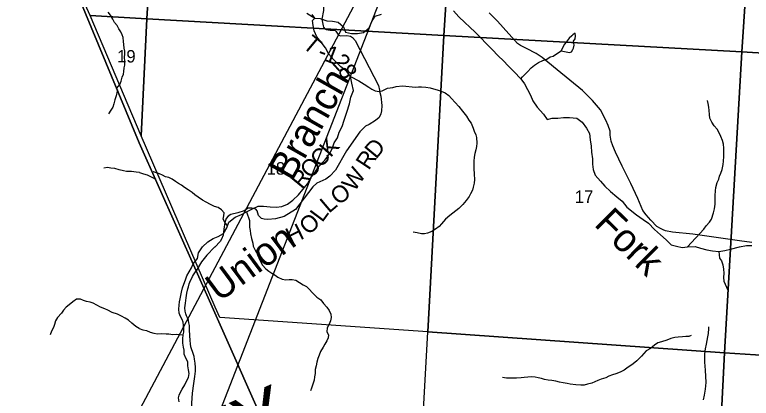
# Model space of a CAD drawing. Extents: x 0 to 34, y 0 to 22.
# Drawn here: x 3.875 to 6.352, y 15.256 to 16.547 of the extents above; entities that cross this region are included whole.
import ezdxf

# ---------------------------------------------------------------- set-up
doc = ezdxf.new("R2010")
doc.units = 0
for name, color, linetype in [('GM_X_County_Text', 7, 'Continuous'), ('GM_X_Minor_Lake', 7, 'Continuous'), ('GM_X_Minor_River', 7, 'Continuous'), ('GM_X_Minor_River_Text', 7, 'Continuous'), ('GM_X_Section', 7, 'Continuous'), ('GM_X_Section_Text', 7, 'Continuous'), ('GM_X_State_Route', 7, 'Continuous'), ('GM_X_Township_Road', 7, 'Continuous'), ('GM_X_Township_Road_Text', 7, 'Continuous'), ('GM_X_Unincorporated', 7, 'Continuous'), ('SH_Cut_Line', 7, 'Continuous'), ('SH_Text', 7, 'Continuous')]:
    doc.layers.add(name, color=color, linetype=linetype)

msp = doc.modelspace()

# ---------------------------------------------------------------- linework, layer by layer
at = {"layer": 'GM_X_Minor_Lake'}
for points in [[(5.7603, 16.4656), (5.761, 16.4766), (5.7595, 16.4853), (5.7523, 16.4789), (5.7482, 16.4755), (5.7402, 16.4683), (5.7296, 16.4547), (5.7231, 16.4471), (5.7126, 16.4254)], [(5.7126, 16.4254), (5.7408, 16.4201), (5.7477, 16.422), (5.7526, 16.4303), (5.7545, 16.4345), (5.7564, 16.4451), (5.7549, 16.4576), (5.7603, 16.4656)]]:
    msp.add_lwpolyline(points, dxfattribs=at)
at = {"layer": 'GM_X_Minor_River'}
for points in [[(4.218, 16.3003), (4.2279, 16.3118), (4.2329, 16.3239), (4.2356, 16.3364), (4.2405, 16.347), (4.2417, 16.3565), (4.2425, 16.3678), (4.2452, 16.3773), (4.2445, 16.3906), (4.2442, 16.4039), (4.245, 16.4141), (4.2447, 16.4247), (4.2425, 16.435), (4.2418, 16.4467), (4.2403, 16.457), (4.2393, 16.4699), (4.2363, 16.4794), (4.2318, 16.4893), (4.225, 16.4995), (4.2187, 16.5106), (4.2104, 16.5212), (4.2044, 16.5319), (4.1969, 16.5456), (4.1886, 16.5555)], [(4.857, 16.5526), (4.8838, 16.535), (4.902, 16.5339), (4.925, 16.527), (4.9436, 16.5259), (4.9625, 16.5224), (4.9806, 16.5068), (4.987, 16.4885), (5.0078, 16.4836), (5.0275, 16.4836), (5.048, 16.4874), (5.0669, 16.5033), (5.0764, 16.5246), (5.0867, 16.5428), (5.1083, 16.5493)], [(5.3506, 16.5601), (5.3691, 16.5399), (5.3887, 16.5212), (5.4061, 16.5056), (5.4235, 16.4881), (5.4431, 16.4691), (5.4609, 16.4508), (5.4805, 16.4299), (5.5009, 16.4086), (5.5187, 16.3922), (5.5345, 16.3751), (5.5553, 16.3549), (5.5772, 16.3317), (5.5893, 16.3142), (5.61, 16.2765), (5.6172, 16.2567), (5.6326, 16.2358), (5.653, 16.2118), (5.6655, 16.1943), (5.6829, 16.1989), (5.7018, 16.1989), (5.7211, 16.2008), (5.7404, 16.2011), (5.7654, 16.1984), (5.7835, 16.1851), (5.7986, 16.1646), (5.8081, 16.1467), (5.8107, 16.1261), (5.8133, 16.1045), (5.8151, 16.0839), (5.8181, 16.0622), (5.818, 16.0444), (5.821, 16.0254), (5.8267, 16.0067), (5.8455, 15.9869), (5.8599, 15.9694), (5.8784, 15.9519), (5.9007, 15.9344), (5.9181, 15.9188), (5.9339, 15.8986), (5.9664, 15.8731), (5.9883, 15.8571), (6.0072, 15.8453), (6.0269, 15.8244), (6.0469, 15.8065)], [(4.4751, 15.7083), (4.489, 15.7259), (4.4924, 15.7449), (4.5061, 15.765), (4.5239, 15.7821), (4.5418, 15.7931), (4.5588, 15.8003), (4.577, 15.811), (4.588, 15.83), (4.5953, 15.8482), (4.6161, 15.8653), (4.6373, 15.874), (4.6548, 15.8835), (4.6741, 15.8938), (4.6931, 15.9021), (4.7112, 15.9021), (4.7336, 15.9002), (4.7544, 15.8994), (4.7729, 15.9017), (4.7923, 15.9093), (4.8101, 15.9222), (4.8298, 15.9404), (4.8442, 15.9583), (4.8594, 15.9776), (4.8704, 15.9974), (4.8845, 16.016), (4.8982, 16.0361), (4.9175, 16.0578), (4.9346, 16.0798), (4.9433, 16.0985), (4.9491, 16.1159), (4.9605, 16.133), (4.9662, 16.1521), (4.9764, 16.1707), (4.9833, 16.1923), (4.9917, 16.219), (5.0005, 16.2471), (5.0058, 16.2691), (5.0138, 16.2923), (5.0082, 16.3167), (5.0041, 16.3387), (4.9916, 16.3562), (4.9716, 16.3718), (4.9486, 16.395), (4.9312, 16.4141), (4.9199, 16.4361), (4.9056, 16.4552), (4.8912, 16.4723), (4.8818, 16.4928), (4.8781, 16.5111), (4.8766, 16.5282), (4.8838, 16.535)], [(4.8838, 16.535), (4.875, 16.5478)], [(5.5772, 16.3317), (5.5826, 16.3384), (5.5996, 16.3548), (5.612, 16.368), (5.623, 16.3768), (5.6362, 16.3863), (5.6517, 16.3931), (5.6646, 16.398), (5.6763, 16.4049), (5.6865, 16.4079), (5.6975, 16.4159), (5.7126, 16.4254)], [(5.0041, 16.3387), (5.0322, 16.3241), (5.0499, 16.3132), (5.0654, 16.3029), (5.076, 16.2965), (5.0866, 16.2908), (5.1006, 16.2885), (5.1108, 16.2912), (5.1286, 16.2999), (5.1467, 16.3026), (5.1573, 16.306), (5.1792, 16.3079), (5.2234, 16.303), (5.2333, 16.3041), (5.2435, 16.3038), (5.2575, 16.303), (5.2718, 16.3004), (5.2839, 16.2981), (5.296, 16.2947), (5.3089, 16.2902), (5.3221, 16.2841), (5.3346, 16.275), (5.344, 16.2655), (5.3561, 16.2519), (5.3682, 16.2378), (5.3811, 16.2219), (5.3947, 16.2056), (5.4026, 16.192), (5.4102, 16.1817), (5.417, 16.1654), (5.4204, 16.1552), (5.4253, 16.1431), (5.4275, 16.1332), (5.4287, 16.1146), (5.4279, 16.1032), (5.426, 16.0919), (5.423, 16.0801), (5.4203, 16.0676), (5.4192, 16.0536), (5.4192, 16.0297), (5.4199, 16.0099), (5.4211, 15.9925), (5.4199, 15.98), (5.4169, 15.9667), (5.415, 15.9569), (5.4082, 15.944), (5.4037, 15.9345), (5.3935, 15.9216), (5.3817, 15.9083), (5.3681, 15.895), (5.3583, 15.8867), (5.3481, 15.8787), (5.3383, 15.8707), (5.3243, 15.8586), (5.3103, 15.843), (5.3027, 15.8335), (5.2903, 15.8252), (5.2782, 15.8172), (5.2634, 15.8119), (5.2528, 15.8096), (5.2426, 15.8092), (5.2283, 15.8123), (5.2147, 15.8149)], [(4.2205, 16.2943), (4.2193, 16.2897), (4.2157, 16.2744), (4.2115, 16.2604), (4.2084, 16.2475), (4.2045, 16.2354), (4.1976, 16.2255), (4.19, 16.2131)], [(6.1377, 15.765), (6.1925, 15.8253), (6.2009, 15.8359), (6.2122, 15.8488), (6.219, 15.8583), (6.2254, 15.8799), (6.2292, 15.8935), (6.2304, 15.9091), (6.2311, 15.9273), (6.2315, 15.9379), (6.2319, 15.9546), (6.2334, 15.9648), (6.2372, 15.9819), (6.2432, 15.9929), (6.2459, 16.0031), (6.2504, 16.0134), (6.2549, 16.0259), (6.2584, 16.0433), (6.2595, 16.0536), (6.2599, 16.0699), (6.2606, 16.0832), (6.2606, 16.0976), (6.2595, 16.1109), (6.2561, 16.1237), (6.2497, 16.137), (6.2455, 16.1473), (6.2372, 16.1613), (6.2281, 16.173), (6.2198, 16.1855), (6.213, 16.1984), (6.2115, 16.2109), (6.2108, 16.2242), (6.2096, 16.2364), (6.207, 16.2485), (6.2047, 16.2584)], [(4.2948, 16.016), (4.2833, 16.0168), (4.2678, 16.0188), (4.2501, 16.0197), (4.2402, 16.0216), (4.2263, 16.0251), (4.2119, 16.029), (4.1983, 16.0306), (4.1862, 16.0322), (4.1741, 16.0304)], [(4.2948, 16.016), (4.3077, 16.011), (4.3197, 16.0079), (4.3333, 16.0013), (4.3465, 15.9944), (4.349, 15.9929)], [(4.5904, 15.836), (4.5817, 15.8487), (4.5753, 15.8589), (4.578, 15.8696), (4.5787, 15.8802), (4.5701, 15.8904), (4.5587, 15.8977), (4.547, 15.9019), (4.5334, 15.9084), (4.5187, 15.916), (4.5062, 15.9225), (4.4915, 15.9332), (4.4809, 15.9412), (4.4711, 15.9481), (4.4586, 15.9572), (4.4454, 15.9656), (4.4355, 15.9728), (4.4257, 15.9786), (4.4159, 15.9858), (4.4038, 15.9931), (4.3925, 15.9988), (4.3815, 16.0011), (4.3717, 16.0065), (4.3615, 16.0114), (4.3516, 16.0149), (4.3418, 16.0176), (4.3399, 16.0176)], [(4.6544, 15.8833), (4.6646, 15.8544), (4.6649, 15.8438), (4.6645, 15.8321), (4.6664, 15.8211), (4.6683, 15.8097), (4.6712, 15.7937), (4.6754, 15.7774), (4.6765, 15.7679), (4.6844, 15.7524), (4.6919, 15.7383), (4.6972, 15.7254), (4.7025, 15.714), (4.7077, 15.7037), (4.719, 15.6919), (4.7296, 15.6839), (4.7394, 15.6767), (4.7504, 15.6706), (4.7602, 15.6637), (4.7742, 15.6568), (4.7871, 15.6541), (4.7973, 15.6552), (4.8079, 15.6556), (4.82, 15.6529), (4.8321, 15.6453), (4.8449, 15.6376), (4.8559, 15.6319), (4.8665, 15.622), (4.8748, 15.6121), (4.8914, 15.5961), (4.9042, 15.5866), (4.9133, 15.5748), (4.925, 15.5622), (4.9321, 15.5512), (4.9382, 15.5383), (4.9396, 15.5273), (4.9373, 15.5159), (4.9324, 15.5053), (4.9252, 15.4928), (4.9248, 15.4792), (4.93, 15.4693), (4.9289, 15.4591), (4.9247, 15.4488), (4.9178, 15.4379), (4.9118, 15.428), (4.9034, 15.4133), (4.8988, 15.4004), (4.8943, 15.389), (4.8912, 15.3773), (4.8889, 15.3644), (4.8858, 15.3523), (4.8858, 15.3394), (4.8827, 15.3276), (4.8816, 15.3163), (4.8759, 15.2992), (4.8732, 15.2898), (4.8698, 15.281)], [(6.0469, 15.8065), (6.0658, 15.7894), (6.0832, 15.7719), (6.1009, 15.7677), (6.1199, 15.7638), (6.1377, 15.765), (6.1638, 15.7668), (6.1812, 15.7607), (6.2024, 15.7558), (6.222, 15.752), (6.2436, 15.7504), (6.2633, 15.7534), (6.283, 15.7572), (6.3125, 15.7656), (6.3364, 15.7701), (6.3542, 15.7697)], [(6.2436, 15.7504), (6.2458, 15.7278), (6.2519, 15.718), (6.2564, 15.7051), (6.2594, 15.6907), (6.2605, 15.677), (6.2594, 15.6626), (6.2605, 15.6501), (6.2734, 15.6197)], [(4.4276, 15.2437), (4.4258, 15.2566), (4.4277, 15.2664), (4.4323, 15.2763), (4.4377, 15.2865), (4.4468, 15.3012), (4.453, 15.3133), (4.4591, 15.325), (4.4618, 15.3391), (4.4593, 15.3516), (4.4571, 15.3649), (4.4575, 15.3785), (4.4497, 15.3911), (4.4448, 15.404), (4.4449, 15.4177), (4.4423, 15.4279), (4.4398, 15.4416), (4.4402, 15.456), (4.4415, 15.4689), (4.443, 15.4784), (4.4435, 15.4878), (4.4424, 15.5004), (4.441, 15.5114), (4.438, 15.5209), (4.4328, 15.5308), (4.4279, 15.5418), (4.4269, 15.5555), (4.4277, 15.5687), (4.4289, 15.5805), (4.4309, 15.5903), (4.4332, 15.6013), (4.4352, 15.6131), (4.439, 15.6271), (4.444, 15.6403), (4.4494, 15.6539), (4.4536, 15.6679), (4.4617, 15.6812), (4.4689, 15.6944), (4.4752, 15.7081)], [(4.2934, 15.4907), (4.282, 15.4968), (4.2689, 15.509), (4.2576, 15.5182), (4.2466, 15.5251), (4.2342, 15.5324), (4.2206, 15.5389), (4.2029, 15.5447), (4.1878, 15.5524), (4.178, 15.557), (4.1629, 15.5628), (4.1512, 15.5693), (4.1384, 15.5758), (4.1279, 15.5793), (4.1162, 15.582), (4.106, 15.5851), (4.0954, 15.5894), (4.0822, 15.5898), (4.07, 15.5804), (4.0575, 15.5699), (4.0476, 15.5623), (4.0388, 15.5525), (4.0316, 15.5423), (4.019, 15.5276), (4.0121, 15.5163), (4.0087, 15.5038), (4.0056, 15.4939), (3.9983, 15.4815), (3.9941, 15.4694)], [(4.2934, 15.4907), (4.3058, 15.4861), (4.3179, 15.4833), (4.33, 15.4787), (4.3424, 15.4745), (4.3553, 15.4729), (4.37, 15.4735), (4.3837, 15.4731), (4.3935, 15.4726), (4.4063, 15.4707), (4.4188, 15.4714), (4.4415, 15.4691)], [(6.2087, 15.4966), (6.2083, 15.49), (6.2076, 15.4733), (6.2057, 15.4623), (6.2027, 15.4506), (6.2004, 15.4381), (6.197, 15.4225), (6.1955, 15.4047), (6.1951, 15.3925), (6.1955, 15.3759), (6.1962, 15.3649), (6.1974, 15.3493), (6.1989, 15.33), (6.1996, 15.3087), (6.1977, 15.2864), (6.1936, 15.2666), (6.1909, 15.2507)], [(6.1497, 15.4669), (6.1429, 15.4634), (6.1324, 15.4631), (6.121, 15.4627), (6.1067, 15.4619), (6.0953, 15.4608), (6.0817, 15.4566), (6.0685, 15.4513), (6.05, 15.4452), (6.0386, 15.4418), (6.0265, 15.4342), (6.0137, 15.4236), (5.9985, 15.4152), (5.983, 15.3978), (5.9675, 15.3822), (5.9547, 15.372), (5.9343, 15.3568), (5.9244, 15.3503), (5.9108, 15.3435), (5.8972, 15.3382), (5.8851, 15.334), (5.8734, 15.3298), (5.8628, 15.3249), (5.8477, 15.3199), (5.8364, 15.3154), (5.8265, 15.3108), (5.8159, 15.3067), (5.8012, 15.3032), (5.7906, 15.2994), (5.7785, 15.2998), (5.7623, 15.3006), (5.7426, 15.3032), (5.7328, 15.3051), (5.7196, 15.3074), (5.7078, 15.31), (5.6946, 15.3127), (5.6814, 15.3149), (5.6693, 15.3164), (5.6564, 15.3191), (5.6462, 15.3221), (5.6356, 15.3248), (5.6254, 15.3267), (5.6141, 15.3278), (5.6009, 15.3267), (5.5884, 15.3259), (5.5782, 15.3247), (5.5631, 15.3236), (5.5529, 15.3232), (5.543, 15.3228), (5.529, 15.3236), (5.5158, 15.3259)]]:
    msp.add_lwpolyline(points, dxfattribs=at)
at = {"layer": 'GM_X_Section'}
for points in [[(3.6608, 17.6237), (4.383, 17.5655), (4.3194, 16.5337), (4.128, 16.5445), (4.0354, 16.7509), (3.8249, 17.2336)], [(4.383, 17.5655), (5.3838, 17.5009), (5.3178, 16.4777), (4.3194, 16.5337)], [(5.3838, 17.5009), (6.388, 17.4386), (6.3205, 16.4222), (5.3178, 16.4777)], [(6.388, 17.4386), (7.3907, 17.3751), (7.3221, 16.3607), (6.3205, 16.4222)], [(4.128, 16.5445), (4.3194, 16.5337), (4.2998, 16.1397)], [(4.3194, 16.5337), (5.3178, 16.4777), (5.2643, 15.4788), (4.5642, 15.5278), (4.5486, 15.5628), (4.2998, 16.1397)], [(5.3178, 16.4777), (6.3205, 16.4222), (6.2624, 15.4089), (5.2643, 15.4788)], [(6.3205, 16.4222), (7.3221, 16.3607), (7.27, 15.3432), (6.2624, 15.4089)], [(6.2624, 15.4089), (6.2103, 14.3869), (5.2076, 14.4458), (5.2643, 15.4788)], [(7.27, 15.3432), (7.2187, 14.3265), (6.2103, 14.3869), (6.2624, 15.4089)]]:
    msp.add_lwpolyline(points, close=True, dxfattribs=at)
at = {"layer": 'GM_X_State_Route'}
msp.add_lwpolyline([(6.354, 15.7806), (6.3131, 15.7863), (6.1555, 15.8083), (6.0869, 15.8153), (6.0644, 15.8197), (6.0563, 15.8223), (6.0471, 15.8271), (6.0342, 15.8344), (6.0143, 15.8554), (5.9989, 15.873), (5.9881, 15.8881), (5.9709, 15.9287), (5.9467, 15.9789), (5.9179, 16.0375), (5.8954, 16.0845), (5.8864, 16.1054), (5.8816, 16.1211), (5.8782, 16.1412), (5.8778, 16.1551), (5.8715, 16.1745), (5.8629, 16.1924), (5.8452, 16.2264), (5.8185, 16.2584), (5.7847, 16.2918), (5.6993, 16.3621), (5.6486, 16.4031), (5.6286, 16.4169), (5.5959, 16.4333), (5.5764, 16.4431), (5.5659, 16.4504), (5.4991, 16.5253), (5.4709, 16.5538)], dxfattribs=at)
at = {"layer": 'GM_X_Township_Road'}
for points in [[(4.9234, 16.6264), (4.9156, 16.6012), (4.9128, 16.5937), (4.9138, 16.5757), (4.9128, 16.5617), (4.9079, 16.5327), (4.9117, 16.5099), (4.9132, 16.5055), (4.9179, 16.4999), (4.9224, 16.497), (4.9362, 16.4952), (4.9495, 16.4952), (4.9521, 16.4936), (4.9547, 16.4913), (4.964, 16.4787), (4.9711, 16.4758), (4.9917, 16.4772), (5.0047, 16.475), (5.0105, 16.4708), (5.0204, 16.4599), (5.0984, 16.3092), (5.1017, 16.2936)], [(5.1017, 16.2936), (5.1034, 16.2858), (5.1061, 16.2731), (5.1098, 16.2411), (5.1084, 16.2233), (5.106, 16.2131), (5.1002, 16.2014), (5.0883, 16.1913), (5.0665, 16.178), (5.0542, 16.1714), (5.0354, 16.1523), (4.9905, 16.0884), (4.9532, 16.0241), (4.9347, 16.0035), (4.9216, 15.993), (4.9011, 15.9842), (4.8904, 15.9802), (4.8773, 15.9671), (4.8186, 15.8913), (4.7815, 15.8679), (4.7518, 15.8596), (4.7264, 15.8577), (4.7139, 15.8587), (4.7053, 15.8615), (4.6989, 15.8665), (4.6952, 15.8715), (4.6919, 15.8791), (4.6905, 15.8871), (4.6853, 15.8929), (4.6724, 15.8954), (4.6599, 15.8952), (4.6466, 15.887), (4.6256, 15.8797), (4.602, 15.874), (4.5925, 15.8688), (4.5855, 15.8606), (4.5812, 15.8474), (4.5782, 15.8254), (4.5756, 15.8045), (4.5705, 15.7917), (4.5658, 15.7834), (4.5474, 15.7649), (4.5467, 15.7642)], [(4.5467, 15.7642), (4.5204, 15.7378), (4.5027, 15.7153), (4.485, 15.6845)], [(4.4684, 15.2043), (4.4723, 15.2732), (4.4767, 15.3051), (4.4804, 15.3292), (4.4822, 15.3464), (4.4824, 15.3593), (4.4816, 15.3737), (4.4798, 15.387), (4.4782, 15.3959), (4.4735, 15.4092), (4.4695, 15.4224), (4.4674, 15.4287), (4.4664, 15.4386), (4.4652, 15.4507), (4.463, 15.4855), (4.462, 15.5012), (4.4608, 15.5095), (4.4589, 15.5184), (4.4559, 15.5267), (4.4529, 15.5332), (4.4501, 15.54), (4.448, 15.5491), (4.4472, 15.5602), (4.4486, 15.5758), (4.4513, 15.594), (4.4535, 15.609), (4.4573, 15.6243), (4.4587, 15.6304), (4.4618, 15.6405), (4.466, 15.652), (4.4703, 15.6605), (4.4731, 15.666), (4.4761, 15.6714), (4.485, 15.6845)]]:
    msp.add_lwpolyline(points, dxfattribs=at)
at = {"layer": 'GM_X_Unincorporated'}
msp.add_lwpolyline([(2.2853, 20.9), (2.1, 20.9), (2.1, 14.1), (2.8399, 14.1), (2.9778, 14.1609), (3.8099, 14.5285), (4.2904, 14.7408), (4.3998, 14.7897), (4.802, 14.9692), (4.4847, 15.685), (4.2937, 16.1161), (4.0882, 16.6114), (3.972, 16.8916), (3.7367, 17.4136), (3.709, 17.484), (3.4011, 18.2653), (3.1249, 18.9173), (3.0781, 19.0279), (2.9956, 19.2227), (2.9553, 19.318), (2.7473, 19.8121), (2.418, 20.5866)], close=True, dxfattribs=at)
msp.add_lwpolyline([(4.0882, 16.6114), (4.2937, 16.1161), (4.4847, 15.685), (4.802, 14.9692), (4.3998, 14.7897), (4.2904, 14.7408), (3.8099, 14.5285), (4.1531, 14.503), (4.2897, 14.5063), (4.438, 14.498), (6.2131, 14.3976), (7.1526, 14.3412), (7.2248, 14.3369), (7.5073, 14.3182), (7.991, 14.2863), (8.4238, 14.2578), (8.9, 14.2264), (8.9, 20.3234)], dxfattribs=at)
at = {"layer": 'SH_Cut_Line'}
for points in [[(2.1, 20.9), (2.1, 14.1), (2.8399, 14.1), (2.9778, 14.1609), (3.8099, 14.5285), (4.2904, 14.7408), (4.3998, 14.7897), (4.802, 14.9692), (4.4847, 15.685), (4.2937, 16.1161), (4.0882, 16.6114)], [(4.0882, 16.6114), (4.2937, 16.1161), (4.4847, 15.685), (4.802, 14.9692), (4.3998, 14.7897), (4.2904, 14.7408), (3.8099, 14.5285), (2.9778, 14.1609), (2.8399, 14.1), (8.9, 14.1), (8.9, 20.9)]]:
    msp.add_lwpolyline(points, dxfattribs=at)
at = {"layer": 'SH_Text'}
msp.add_lwpolyline([(4.1319, 14.1), (4.1319, 14.9089), (5.3159, 17.1435)], close=True, dxfattribs=at)

# ---------------------------------------------------------------- texts
at = {"layer": 'GM_X_County_Text'}
msp.add_text('SCIOTO COUNTY', height=0.189394, rotation=23.8999, dxfattribs=at).set_placement((2.8904, 14.2774))
at = {"layer": 'GM_X_Minor_River_Text'}
for s, height, rotation, p in [('Branch', 0.09468, 60.4883, (4.807, 15.9827)), ('Fork', 0.09469, 315.4945, (5.8206, 15.8387)), ('Union', 0.09469, 36.4864, (4.5624, 15.5775))]:
    msp.add_text(s, height=height, rotation=rotation, dxfattribs=at).set_placement(p)
at = {"layer": 'GM_X_Section_Text'}
for s, p in [('19', (4.2191, 16.3863)), ('18', (4.722, 16.0088)), ('17', (5.7587, 15.9135))]:
    msp.add_text(s, height=0.04186, rotation=0, dxfattribs=at).set_placement(p)
at = {"layer": 'GM_X_Township_Road_Text'}
for s, rotation, p in [('T', 320.2954, (4.8398, 16.4394)), ('1', 338.9616, (4.912, 16.3938)), ('-', 339.3316, (4.8902, 16.402)), ('2', 311.7048, (4.9388, 16.3852)), ('8', 297.5659, (4.96, 16.3621)), ('K', 48.5404, (4.9369, 16.0642)), ('D', 50.3178, (5.0902, 16.0589)), ('C', 47.0413, (4.904, 16.0288)), ('R', 56.5719, (5.0655, 16.0212)), ('O', 47.3872, (4.8702, 15.9921)), ('W', 55.7065, (5.0176, 15.9484)), ('R', 50.7166, (4.8413, 15.9566)), ('O', 36.8342, (4.9635, 15.9037)), ('L', 40.182, (4.9317, 15.8768)), ('L', 53.2926, (4.9087, 15.8453)), ('O', 41.2422, (4.8623, 15.8027)), ('H', 25.915, (4.8035, 15.7717))]:
    msp.add_text(s, height=0.0568, rotation=rotation, dxfattribs=at).set_placement(p)

doc.saveas('drawing.dxf')
